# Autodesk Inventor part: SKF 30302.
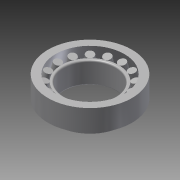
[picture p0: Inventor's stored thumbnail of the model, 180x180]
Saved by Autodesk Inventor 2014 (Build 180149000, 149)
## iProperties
Shininess: 20.0
Length Units: 11269
Angle Units: 11279
Time Units: 11290
Mass Units: 11283
Length Display Precision: 3
Angle Display Precision: 2
Created: 2001-02
Part Number: SKF 30302.
Material: Steel, Mild
Description: Bearing SKF 30302.
Document SubType Name: Modeling
Density: 7.86 g/cm^3
Appearance: Steel
Density: 7.86
Volumn: 10.214056141118272
Area: 88.6561878138125
PropertySet Name: Model Information
Control State: 0
Master: False
Checked Out: False
BOM1: Bearing
BOM2: SKF 30302
ProtocolID: P00020918080728916
Protocol: P00020918080728916<@PID>[Version]<@EL>Version=2.2<@EL>[Synchronize]<@EL>ChangedVars=<@EL>[Calc]<@EL>CalcName=BEARINGS<@EL>Optim=1<@EL>WizardMode=2<@EL>ScnVisibl
Author: PaulN
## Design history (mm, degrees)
node "WorkPlane4"
node "WorkPlane1"
workplane "Work Plane3"
node "WorkPlane2"
node "Sketch1"
node "WorkPoint1"
node "Sketch2"
node "WorkPoint2"
extrude "ExtrusionBlind1" new body distance "d3" = 23 (= prf_b); taper "d4" = 0 deg
  node "Sketch3" dims "d2" = 72.5 (= msp_dd2)
node "WorkAxis1"
sketch "Sketch4"
  geometry: C1 r 36.25 at (0, 0) reference
hole "Hole1" sketch "Sketch4" diameter "d6" = 55 (= prf_d); stored, may be unused: countersink angle "d10" = 60 deg, drill point angle "d12" = 118 deg; dims "d7" = 6, "d8" = 4, "d9" = 2, "d11" = 8
sketch "Sketch5"
  geometry: L1 (38.121, 23)-(34.062, 23); L2 (34.062, 23)-(34.062, 23.734); L3 (30.465, 22.969)-(34.062, 23.734); L4 (30.465, 22.969)-(33.285, 5.171); L5 (33.285, 5.171)-(38.121, 6.199); L6 (38.121, 23)-(38.121, 6.199); L7 (31.875, 14.07)-(36.25, 15); L8 (34.823, 21.715)-(37.782, 7.79); L9 (0, 15.439)-(0, -16.364); L10 (-36.25, 23)-(36.25, 23) reference; L11 (-36.25, 0)-(36.25, 0) reference; L12 (0, 29.364)-(0, -16.364); L13 (0, -25.509)-(0, 38.509) reference
  constraints: 20 end point, 3 collinear, 3 parallel, 2 perpendicular, 2 point on line, 2 vertical, 1 horizontal, 1 midpoint
  dimensions: "d14" = 12 deg angle of L9 L8 (= prf_alfa); "d17" = 17.7978 vertical distance of L3.start L4.end (computed from msp_l0, prf_alfa, msp_ang); "d37" = 72.5 diameter of L7.end L12 (= msp_mdtds); "d42" = 8.8989 vertical distance of L4.end L7.start (= d23); "d49" = 2.9944 deg angle of L8 L4 (= msp_ang); "d54" = 15 distance from line of L11 L7.end (= 0.5 x prf_t); "d55" = 4.375 horizontal distance of L7.start L7.end (= 0.5 x msp_dd0); "d56" = 68.125 diameter of L1.end L13 (= msp_mdtds - 0.5 x msp_dd0)
revolve "RevolutionFull1" sketch "Sketch5" stored, may be unused: angle "d18" = 360 deg
sketch "Sketch6"
  geometry: L1 (33.285, 5.171)-(38.121, 6.199); L2 (33.285, 5.171)-(30.465, 22.969); L3 (30.465, 22.969)-(34.379, 23.801); L4 (38.121, 6.199)-(34.379, 23.801); L5 (34.614, 22.696)-(37.676, 8.293); L6 (31.875, 14.07)-(36.25, 15); L7 (0, 29.364)-(0, -16.364); L8 (-36.25, 0)-(36.25, 0) reference; L9 (38.121, 6.199)-(34.379, 23.801); L10 (0, -25.509)-(0, 38.509) reference; L11 (33.285, 5.171)-(30.465, 22.969) reference; L12 (36.25, 5.801)-(33.285, 5.171) reference; L13 (30.465, 22.969)-(30.611, 23) reference
  constraints: 17 end point, 3 point on line, 2 collinear, 2 midpoint, 2 parallel, 1 perpendicular
  dimensions: "d20" = 12 deg angle of L7 L5 (= prf_alfa); "d23" = 8.8989 vertical distance of L6.start L1.start (computed from msp_ang, prf_alfa, msp_l0); "d46" = 72.5 diameter of L6.end L7 (= d37); "d47" = 17.7978 vertical distance of L1.start L2.end (= d17)
revolve "RevolutionFull2" sketch "Sketch6" stored, may be unused: angle "d24" = 360 deg
pattern_circular "PolarArray1" dims angle "d27" = 360 deg
sketch "Sketch7"
  geometry: L1 (45, 7)-(43.017, 7); L2 (45, 30)-(45, 7); L3 (36.857, 30)-(45, 30); L4 (43.017, 7)-(36.857, 30); L5 (-36.25, 0)-(36.25, 0) reference; L6 (0, 29.364)-(0, -16.364); L7 (0, 29.364)-(0, -16.364); L8 (0, -25.636)-(0, 39.273) reference; L9 (42.956, 7.227)-(38.294, 24.633) reference; L10 (35, 30)-(-35, 30) reference
  constraints: 12 end point, 2 horizontal, 1 collinear, 1 parallel, 1 vertical
  dimensions: "d29" = 23 distance of L2.start L1.start (= prf_cc); "d44" = 90 diameter of L2 L6 (= prf_dd); "d45" = 30 distance between parallel lines of L5 L3 (= prf_t); "d63" = 0.0001 distance between parallel lines of L4 L9
fillet "Fillet2" dims "d33" = 1.5 (= prf_r)
fillet "Fillet3" dims "d34" = 1.5 (= prf_r)
revolve "Revolution4" stored, may be unused: angle "d62" = 90 deg
body "Solid1"
other parameters: "prf_b" = 23 [user parameter; used in 1 equation term], "prf_dd" = 90 [user parameter; used in 4 equation terms], "prf_d" = 55 [user parameter; used in 4 equation terms], "msp_dd2" = 72.5 (= 0.5 x prf_d + 0.5 x prf_dd) [user parameter; used in 1 equation term], "prf_t" = 30 [user parameter; used in 3 equation terms], "prf_r" = 1.5 [user parameter; used in 2 equation terms], "prf_cc" = 23 [user parameter; used in 2 equation terms], "msp_dd0" = 8.75 (= -0.25 x prf_d + 0.25 x prf_dd) [user parameter; used in 5 equation terms], "msp_mdtds" = 72.5 (= 0.5 x prf_d + 0.5 x prf_dd) [user parameter; used in 3 equation terms], "prf_alfa" = 12 deg [user parameter; used in 5 equation terms], "msp_l0" = 18.4 (= 0.8 x prf_cc) [user parameter; used in 3 equation terms], "msp_ang" = 2.9944 deg (computed from msp_l0, msp_dd0) [user parameter; used in 4 equation terms], "msp_pom2" = 2.61702 (= prf_alfa + msp_ang) [user parameter; used in 1 equation term], "msp_dd0a" = 4.52921 (computed from msp_dd0, msp_pom2) [user parameter], "d1" = 31 (derived), "d5" = 0, "d13" = 12 deg (derived), "d15" = 0.01098 (derived), "d16" = 9.38802 (derived), "d19" = 12 deg (derived), "d21" = 0.01098 (derived), "d22" = 4.69401 (derived), "d28" = 12 (derived), "d30" = 2.10538 (derived)
